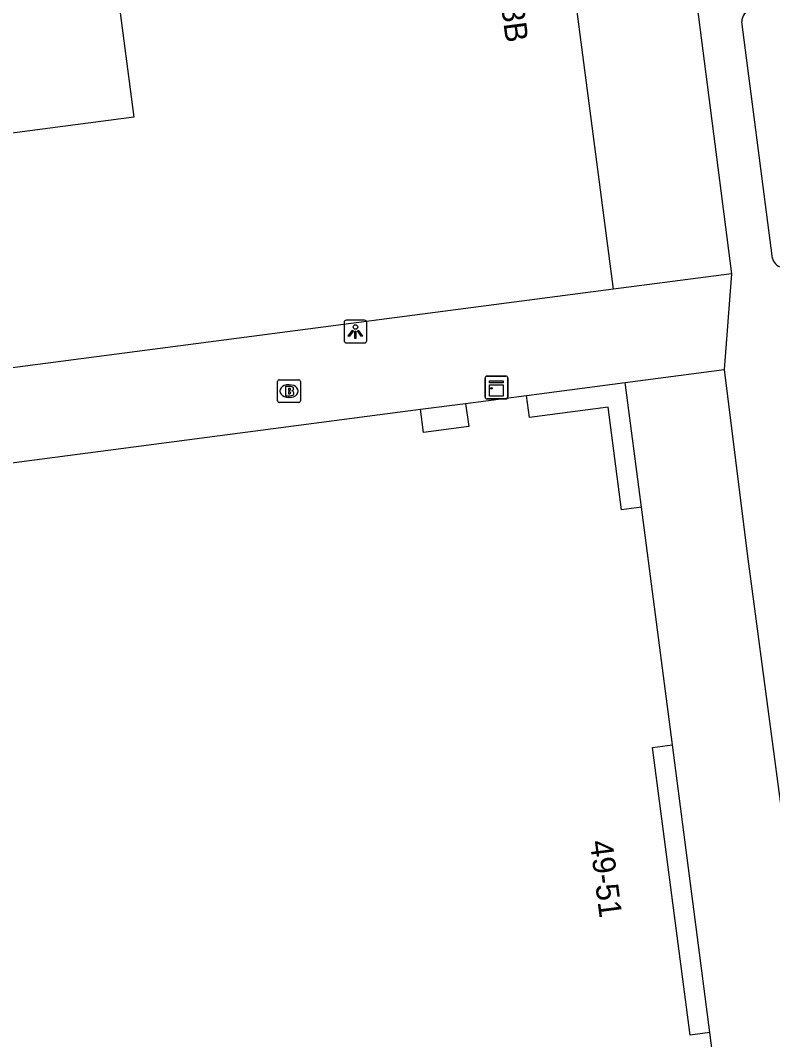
# Model space of a CAD drawing. Extents: x 160557 to 161245, y 385330 to 386505.
# Drawn here: x 161072.59 to 161105.66, y 385687.52 to 385732.31 of the extents above; entities that cross this region are included whole.
import ezdxf

# ---------------------------------------------------------------- set-up
doc = ezdxf.new("R2010")
doc.units = 0
for name, color, linetype in [('IMGEO_Brandkraan', 7, 'Continuous'), ('IMGEO_Kast', 7, 'Continuous'), ('IMGEO_Lichtpunt', 7, 'Continuous'), ('IMGEO_Pand', 7, 'Continuous'), ('IMGEO_Pand_nummerreeks', 7, 'Continuous'), ('IMGEO_Voetpad_open', 7, 'Continuous')]:
    doc.layers.add(name, color=color, linetype=linetype)

msp = doc.modelspace()

# ---------------------------------------------------------------- linework, layer by layer
at = {"layer": 'IMGEO_Brandkraan'}
for p, q in [((161083.898, 385715.594), (161083.898, 385716.446)), ((161083.973, 385716.52), (161084.825, 385716.52)), ((161084.899, 385716.446), (161084.899, 385715.594)), ((161084.386, 385716.3), (161084.411, 385716.3)), ((161084.409, 385715.74), (161084.384, 385715.74)), ((161084.825, 385715.52), (161083.973, 385715.52))]:
    msp.add_line(p, q, dxfattribs=at)
for points in [[(161083.898, 385715.594), (161083.898, 385716.446)], [(161083.973, 385716.52), (161084.825, 385716.52)], [(161084.899, 385716.446), (161084.899, 385715.594)], [(161084.246, 385716.22), (161084.246, 385715.82), (161084.459, 385715.82)], [(161084.477, 385716.22), (161084.246, 385716.22)], [(161084.425, 385716.139), (161084.371, 385716.139), (161084.371, 385716.063)], [(161084.371, 385716.063), (161084.424, 385716.063)], [(161084.433, 385715.987), (161084.371, 385715.987), (161084.371, 385715.906)], [(161084.371, 385715.906), (161084.433, 385715.906)], [(161084.825, 385715.52), (161083.973, 385715.52)]]:
    msp.add_lwpolyline(points, dxfattribs=at)
for centre, radius, start, end in [((161083.975, 385716.444), 0.0765, 91.552, 178.448), ((161083.975, 385716.444), 0.0765, 91.552, 178.448), ((161084.823, 385716.444), 0.0765, 1.552, 88.448), ((161084.823, 385716.444), 0.0765, 1.552, 88.448), ((161084.426, 385716.101), 0.0379, 267.8285, 90.9355), ((161084.434, 385715.946), 0.0404, 269.8759, 90.5077), ((161084.481, 385716.075), 0.145, 59.4692, 91.5367), ((161084.506, 385716.122), 0.0922, 285.5137, 58.1501), ((161084.511, 385715.93), 0.105, 301.3115, 78.989), ((161083.975, 385715.596), 0.0765, 181.552, 268.448), ((161083.975, 385715.596), 0.0765, 181.552, 268.448), ((161084.465, 385716.071), 0.251, 268.6676, 293.5347), ((161084.823, 385715.596), 0.0765, 271.552, 358.448), ((161084.823, 385715.596), 0.0765, 271.552, 358.448)]:
    msp.add_arc(centre, radius, start, end, dxfattribs=at)
for centre, major_axis, ratio, start_param, end_param in [((161084.385, 385716.02), (-0.387, 0.002), 0.722429, 4.712389, 7.853982), ((161084.41, 385716.02), (-0.39, 0.002), 0.717154, 1.570796, 4.712389)]:
    msp.add_ellipse(centre, major_axis=major_axis, ratio=ratio, start_param=start_param, end_param=end_param, dxfattribs=at)
at = {"layer": 'IMGEO_Kast'}
for p, q in [((161093.02, 385715.754), (161093.02, 385716.595)), ((161093.02, 385716.595), (161093.02, 385715.754)), ((161093.095, 385716.679), (161093.936, 385716.679)), ((161093.936, 385716.679), (161093.095, 385716.679)), ((161094.02, 385716.604), (161094.02, 385715.763)), ((161094.02, 385715.763), (161094.02, 385716.604)), ((161093.945, 385715.679), (161093.104, 385715.679)), ((161093.104, 385715.679), (161093.945, 385715.679))]:
    msp.add_line(p, q, dxfattribs=at)
for points in [[(161093.215, 385716.469), (161093.815, 385716.469), (161093.815, 385716.384), (161093.215, 385716.384), (161093.215, 385716.469)], [(161093.215, 385716.294), (161093.815, 385716.294), (161093.815, 385715.805), (161093.215, 385715.805), (161093.215, 385716.294)]]:
    msp.add_lwpolyline(points, dxfattribs=at)
msp.add_circle((161093.299, 385716.143), 0.0377, dxfattribs=at)
for centre, start, end in [((161093.098, 385716.601), 92.4484, 184.2845), ((161093.098, 385716.601), 92.4484, 184.2845), ((161093.942, 385716.601), 2.4484, 94.2845), ((161093.942, 385716.601), 2.4484, 94.2845), ((161093.098, 385715.757), 182.4484, 274.2845), ((161093.098, 385715.757), 182.4484, 274.2845), ((161093.942, 385715.757), 272.4484, 4.2845), ((161093.942, 385715.757), 272.4484, 4.2845)]:
    msp.add_arc(centre, 0.0779, start, end, dxfattribs=at)
at = {"layer": 'IMGEO_Lichtpunt'}
for p, q in [((161087.722, 385719.136), (161086.914, 385719.136)), ((161087.722, 385719.136), (161086.914, 385719.136)), ((161086.82, 385719.041), (161086.82, 385718.234)), ((161086.82, 385719.041), (161086.82, 385718.234)), ((161087.816, 385718.234), (161087.816, 385719.041)), ((161087.816, 385718.234), (161087.816, 385719.041)), ((161086.914, 385718.14), (161087.722, 385718.14)), ((161086.914, 385718.14), (161087.722, 385718.14))]:
    msp.add_line(p, q, dxfattribs=at)
for points in [[(161087.194, 385718.705), (161087.233, 385718.677), (161087.045, 385718.415), (161087.007, 385718.442), (161087.194, 385718.705)], [(161087.406, 385718.677), (161087.444, 385718.704), (161087.631, 385718.442), (161087.592, 385718.414), (161087.406, 385718.677)], [(161087.296, 385718.657), (161087.343, 385718.657), (161087.343, 385718.335), (161087.296, 385718.335), (161087.296, 385718.657)]]:
    msp.add_lwpolyline(points, dxfattribs=at)
msp.add_circle((161087.319, 385718.839), 0.0994, dxfattribs=at)
for centre, start, end in [((161086.914, 385719.041), 90, 180), ((161086.914, 385719.041), 90, 180), ((161087.722, 385719.041), 0, 90), ((161087.722, 385719.041), 0, 90), ((161086.914, 385718.234), 180, 270), ((161086.914, 385718.234), 180, 270), ((161087.722, 385718.234), 270, 0), ((161087.722, 385718.234), 270, 360)]:
    msp.add_arc(centre, 0.0946, start, end, dxfattribs=at)
at = {"layer": 'IMGEO_Pand'}
for points in [[(161098.665, 385720.503), (161095.436, 385745.136), (161094.985, 385745.077)], [(161094.985, 385745.077), (161080.694, 385743.204), (161080.504, 385744.655), (161075.485, 385743.997), (161076.135, 385739.04), (161077.573, 385728.065), (161066.743, 385726.646)], [(161098.665, 385720.503), (161068.084, 385716.495)], [(161092.164, 385715.482), (161094.841, 385715.832)], [(161099.893, 385710.914), (161099.022, 385710.801), (161098.432, 385715.315), (161094.968, 385714.862), (161094.841, 385715.832)], [(161061.683, 385711.481), (161067.611, 385712.273), (161090.181, 385715.223)], [(161092.164, 385715.482), (161092.298, 385714.461), (161090.315, 385714.202), (161090.181, 385715.223)], [(161101.258, 385700.471), (161099.893, 385710.914)], [(161102.902, 385687.829), (161102.038, 385687.716), (161100.387, 385700.358), (161101.258, 385700.471)], [(161103.155, 385685.895), (161102.902, 385687.829)]]:
    msp.add_lwpolyline(points, dxfattribs=at)
at = {"layer": 'IMGEO_Voetpad_open'}
for points in [[(161100.53, 385747.059), (161103.849, 385721.182)], [(161105.661, 385721.844), (161104.309, 385732.248)], [(161103.849, 385721.182), (161098.665, 385720.503)], [(161103.849, 385721.182), (161103.528, 385716.968)], [(161099.176, 385716.399), (161103.528, 385716.968)], [(161103.528, 385716.968), (161104.544, 385708.871), (161105.47, 385701.933), (161107.028, 385690.183), (161107.754, 385684.63), (161108.994, 385675.141), (161109.438, 385671.741)], [(161094.841, 385715.832), (161099.176, 385716.399)], [(161099.893, 385710.914), (161099.176, 385716.399)], [(161090.181, 385715.223), (161092.164, 385715.482)], [(161102.902, 385687.829), (161101.258, 385700.471)]]:
    msp.add_lwpolyline(points, dxfattribs=at)
for centre, radius, start, end in [((161104.83, 385732.266), 0.521, 102.817, 181.9932), ((161106.129, 385721.944), 0.479, 192.0028, 275.2667)]:
    msp.add_arc(centre, radius, start, end, dxfattribs=at)

# ---------------------------------------------------------------- texts
at = {"layer": 'IMGEO_Pand_nummerreeks'}
for s, rotation, p in [('53-53B', 277.468, (161093.382, 385735.573)), ('49-51', 277.4405, (161097.619, 385696.226))]:
    msp.add_text(s, height=1, rotation=rotation, dxfattribs=at).set_placement(p)

doc.saveas('drawing.dxf')
